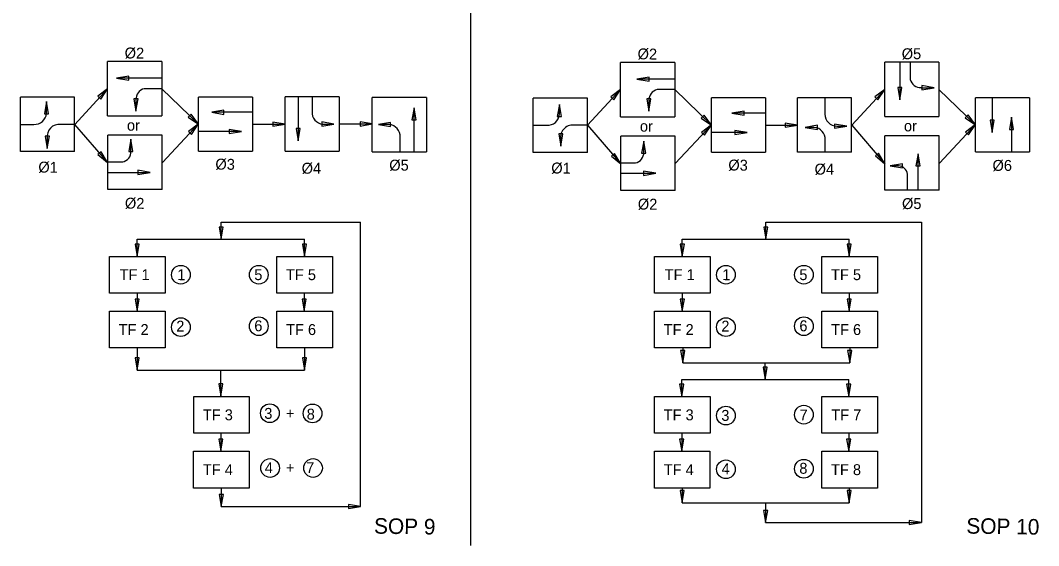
# Model space of a CAD drawing. Extents: x 10027 to 10796, y 10033 to 10528.
# Drawn here: x 10043.8 to 10370.4, y 10033.4 to 10201.8 of the extents above; entities that cross this region are included whole.
import ezdxf

# ---------------------------------------------------------------- set-up
doc = ezdxf.new("R2010")
doc.units = 0
for name, color, linetype in [('AdhocPoint_dp', 7, 'Continuous'), ('Default', 7, 'Continuous'), ('Dimension', 7, 'Continuous'), ('DSIndex', 7, 'Continuous'), ('PlotBorder_dp', 7, 'Continuous')]:
    doc.layers.add(name, color=color, linetype=linetype)

msp = doc.modelspace()

# ---------------------------------------------------------------- linework, layer by layer
at = {"layer": 'AdhocPoint_dp'}
msp.add_line((10188.25, 10033.43), (10188.25, 10528.43), dxfattribs=at)
at = {"layer": 'Default'}
for p, q in [((10071.81, 10171.23), (10071.81, 10188.62)), ((10089.2, 10188.62), (10071.81, 10188.62)), ((10089.2, 10188.62), (10089.2, 10171.23)), ((10236.32, 10170.93), (10236.32, 10188.33)), ((10253.71, 10188.33), (10236.32, 10188.33)), ((10253.71, 10188.33), (10253.71, 10170.93)), ((10321.01, 10171.01), (10321.01, 10188.4)), ((10338.41, 10188.4), (10321.01, 10188.4)), ((10325.85, 10188.4), (10325.85, 10176.39)), ((10329.22, 10188.4), (10329.22, 10182.92)), ((10338.41, 10188.4), (10338.41, 10171.01)), ((10089.21, 10183.29), (10074.69, 10183.29)), ((10253.72, 10183), (10241.53, 10183)), ((10061.27, 10168.48), (10071.81, 10179.92)), ((10089.21, 10179.92), (10083.54, 10179.92)), ((10089.21, 10179.92), (10100.91, 10168.55)), ((10225.72, 10168.19), (10236.32, 10179.69)), ((10253.72, 10179.63), (10248.05, 10179.63)), ((10253.72, 10179.63), (10265.42, 10168.26)), ((10310.44, 10168.23), (10321.01, 10179.71)), ((10338.41, 10179.71), (10350.11, 10168.33)), ((10061.21, 10177.18), (10043.81, 10177.18)), ((10043.81, 10159.78), (10043.81, 10177.18)), ((10061.21, 10159.78), (10061.21, 10177.18)), ((10080.88, 10176.37), (10080.88, 10172.72)), ((10100.91, 10159.85), (10100.91, 10177.25)), ((10118.3, 10177.25), (10100.91, 10177.25)), ((10118.3, 10177.25), (10118.3, 10159.85)), ((10128.71, 10159.91), (10128.71, 10177.3)), ((10146.1, 10177.3), (10128.71, 10177.3)), ((10132.91, 10177.3), (10132.91, 10163.2)), ((10137.36, 10177.3), (10137.36, 10172.6)), ((10146.1, 10177.3), (10146.1, 10159.91)), ((10156.66, 10159.7), (10156.66, 10177.1)), ((10174.06, 10177.1), (10156.66, 10177.1)), ((10174.06, 10177.1), (10174.06, 10159.7)), ((10225.72, 10176.88), (10208.33, 10176.88)), ((10208.33, 10159.49), (10208.33, 10176.88)), ((10225.72, 10159.49), (10225.72, 10176.88)), ((10265.42, 10159.56), (10265.42, 10176.96)), ((10282.81, 10176.96), (10265.42, 10176.96)), ((10282.81, 10176.96), (10282.81, 10159.56)), ((10310.41, 10176.96), (10293.02, 10176.96)), ((10293.02, 10159.56), (10293.02, 10176.96)), ((10301.82, 10176.96), (10301.82, 10171.74)), ((10310.41, 10159.56), (10310.41, 10176.96)), ((10350.11, 10159.64), (10350.11, 10177.03)), ((10367.51, 10177.03), (10350.11, 10177.03)), ((10355.51, 10177.03), (10355.51, 10165.9)), ((10367.51, 10177.03), (10367.51, 10159.64)), ((10052.17, 10171.99), (10052.17, 10175.79)), ((10170.07, 10159.7), (10170.07, 10173.8)), ((10071.81, 10171.23), (10089.2, 10171.23)), ((10118.3, 10172.36), (10105.18, 10172.36)), ((10216.68, 10171.7), (10216.68, 10172.12)), ((10236.32, 10170.93), (10253.71, 10170.93)), ((10282.81, 10172.07), (10272.02, 10172.07)), ((10321.01, 10171.01), (10338.41, 10171.01)), ((10361.67, 10170.77), (10361.67, 10159.64)), ((10043.81, 10168.48), (10048.16, 10168.48)), ((10061.21, 10168.48), (10056.7, 10168.48)), ((10061.21, 10168.48), (10071.74, 10156.28)), ((10089.36, 10156.28), (10100.85, 10168.55)), ((10118.3, 10168.55), (10128.71, 10168.55)), ((10140.87, 10168.58), (10142.01, 10168.58)), ((10142.01, 10168.58), (10144.37, 10168.58)), ((10146.1, 10168.61), (10156.66, 10168.61)), ((10160.98, 10168.42), (10158.62, 10168.42)), ((10162.12, 10168.42), (10160.98, 10168.42)), ((10208.33, 10168.19), (10212.67, 10168.19)), ((10225.72, 10168.19), (10221.79, 10168.19)), ((10225.72, 10168.19), (10236.4, 10155.81)), ((10253.87, 10155.98), (10265.42, 10168.32)), ((10282.81, 10168.26), (10293.02, 10168.26)), ((10310.44, 10168.23), (10321.1, 10155.88)), ((10338.56, 10156.06), (10350.11, 10168.4)), ((10052.45, 10164.03), (10052.45, 10160.76)), ((10089.29, 10164.97), (10071.89, 10164.97)), ((10071.89, 10147.58), (10071.89, 10164.97)), ((10079.22, 10160.02), (10079.22, 10163.73)), ((10089.29, 10147.58), (10089.29, 10164.97)), ((10114.71, 10166.19), (10101.12, 10166.19)), ((10165.63, 10159.7), (10165.63, 10164.41)), ((10253.8, 10164.68), (10236.4, 10164.68)), ((10236.4, 10147.29), (10236.4, 10164.68)), ((10243.73, 10159.57), (10243.73, 10163.12)), ((10253.8, 10147.29), (10253.8, 10164.68)), ((10276.89, 10165.9), (10265.42, 10165.9)), ((10301.91, 10159.56), (10301.91, 10163.52)), ((10338.49, 10164.76), (10321.1, 10164.76)), ((10321.1, 10147.36), (10321.1, 10164.76)), ((10338.49, 10147.36), (10338.49, 10164.76)), ((10061.21, 10159.78), (10043.81, 10159.78)), ((10100.91, 10159.85), (10118.3, 10159.85)), ((10128.71, 10159.91), (10146.1, 10159.91)), ((10156.66, 10159.7), (10174.06, 10159.7)), ((10071.89, 10156.46), (10076.67, 10156.46)), ((10225.72, 10159.49), (10208.33, 10159.49)), ((10265.42, 10159.56), (10282.81, 10159.56)), ((10310.41, 10159.56), (10293.02, 10159.56)), ((10331.7, 10147.36), (10331.7, 10159.06)), ((10350.11, 10159.64), (10367.51, 10159.64)), ((10236.4, 10156.16), (10241.05, 10156.16)), ((10071.89, 10153.09), (10085.41, 10153.09)), ((10236.4, 10152.8), (10247.59, 10152.8)), ((10328.34, 10147.36), (10328.34, 10152.52)), ((10089.29, 10147.58), (10071.89, 10147.58)), ((10253.8, 10147.29), (10236.4, 10147.29)), ((10338.49, 10147.36), (10321.1, 10147.36)), ((10108.19, 10131.66), (10108.19, 10137.16)), ((10108.19, 10137.16), (10152.95, 10137.16)), ((10282.88, 10131.66), (10282.88, 10137.16)), ((10282.88, 10137.16), (10332.81, 10137.16)), ((10332.81, 10137.16), (10332.81, 10040.82)), ((10081.3, 10126.17), (10081.3, 10131.66)), ((10081.3, 10131.66), (10134.96, 10131.66)), ((10134.96, 10126.17), (10134.96, 10131.66)), ((10256.11, 10126.17), (10256.11, 10131.66)), ((10256.11, 10131.66), (10309.65, 10131.66)), ((10309.65, 10126.17), (10309.65, 10131.66)), ((10081.3, 10114.41), (10081.3, 10108.58)), ((10134.84, 10114.41), (10134.84, 10108.58)), ((10256.11, 10114.41), (10256.11, 10108.58)), ((10309.65, 10114.41), (10309.65, 10108.58)), ((10081.3, 10096.82), (10081.3, 10089.73)), ((10134.96, 10096.82), (10134.96, 10089.73)), ((10256.24, 10096.82), (10256.24, 10092.07)), ((10309.79, 10096.82), (10309.79, 10092.07)), ((10256.24, 10092.07), (10309.79, 10092.07)), ((10282.69, 10086.74), (10282.69, 10092.07)), ((10081.3, 10089.73), (10134.96, 10089.73)), ((10108.13, 10081.24), (10108.13, 10089.73)), ((10255.92, 10081.24), (10255.92, 10086.74)), ((10255.92, 10086.74), (10309.47, 10086.74)), ((10309.47, 10081.24), (10309.47, 10086.74)), ((10108.13, 10069.49), (10108.13, 10063.66)), ((10255.92, 10069.49), (10255.92, 10063.66)), ((10309.47, 10069.49), (10309.47, 10063.66)), ((10108.26, 10051.9), (10108.26, 10045.94)), ((10256.06, 10051.9), (10256.06, 10047.15)), ((10309.6, 10051.9), (10309.6, 10047.15)), ((10108.26, 10045.94), (10152.95, 10045.94)), ((10256.06, 10047.15), (10309.6, 10047.15)), ((10282.83, 10047.15), (10282.83, 10040.82)), ((10282.83, 10040.82), (10332.81, 10040.82))]:
    msp.add_line(p, q, dxfattribs=at)
for centre, radius, start, end in [((10332.57, 10183.69), 3.44, 192.998, 272.3331), ((10084.32, 10176.57), 3.44, 102.998, 183.455), ((10248.83, 10176.28), 3.44, 102.998, 182.423), ((10048.4, 10172.25), 3.78, 266.3242, 356.0955), ((10141.13, 10172.35), 3.78, 176.3242, 266.0955), ((10212.91, 10171.96), 3.78, 266.3242, 356.0955), ((10305.7, 10171.8), 3.88, 180.9326, 269.1625), ((10056.29, 10164.62), 3.88, 83.8256, 188.6991), ((10161.86, 10164.65), 3.78, 356.3242, 86.0955), ((10220.95, 10164.39), 3.88, 77.6405, 189.221), ((10298.14, 10163.76), 3.78, 356.3242, 86.0955), ((10076.07, 10159.59), 3.16, 278.4278, 5.0512), ((10240.58, 10159.29), 3.16, 278.4278, 5.0512), ((10325.21, 10152.06), 3.16, 8.4277, 86.4044)]:
    msp.add_arc(centre, radius, start, end, dxfattribs=at)
at = {"layer": 'Dimension'}
for p, q in [((10332.71, 10180.25), (10336.85, 10180.25)), ((10245.39, 10176.14), (10245.39, 10172.77)), ((10216.68, 10172.12), (10216.68, 10174.9)), ((10298.39, 10167.53), (10295.52, 10167.53)), ((10305.64, 10167.92), (10308.83, 10167.92)), ((10217.12, 10163.77), (10217.12, 10161.49)), ((10325.41, 10155.22), (10322.78, 10155.22)), ((10152.95, 10045.94), (10152.95, 10137.16))]:
    msp.add_line(p, q, dxfattribs=at)
for centre in [(10095.28, 10120.29), (10120.28, 10120.29), (10270.09, 10120.29), (10295.09, 10120.29), (10095.28, 10103.48), (10120.28, 10103.77), (10270.09, 10103.48), (10295.09, 10103.77), (10123.83, 10075.89), (10137.51, 10075.82), (10270.09, 10075.12), (10295.09, 10075.41), (10123.9, 10058.31), (10137.68, 10058.31), (10270.09, 10057.9), (10295.09, 10058.08)]:
    msp.add_circle(centre, 3, dxfattribs=at)
at = {"layer": 'DSIndex'}
for points in [[(10072.39, 10126.17), (10090.21, 10126.17), (10090.21, 10114.41), (10072.39, 10114.41)], [(10126.04, 10126.17), (10143.87, 10126.17), (10143.87, 10114.41), (10126.04, 10114.41)], [(10247.2, 10126.17), (10265.02, 10126.17), (10265.02, 10114.41), (10247.2, 10114.41)], [(10300.85, 10126.17), (10318.68, 10126.17), (10318.68, 10114.41), (10300.85, 10114.41)], [(10072.39, 10108.58), (10090.21, 10108.58), (10090.21, 10096.82), (10072.39, 10096.82)], [(10126.04, 10108.58), (10143.87, 10108.58), (10143.87, 10096.82), (10126.04, 10096.82)], [(10247.2, 10108.58), (10265.02, 10108.58), (10265.02, 10096.82), (10247.2, 10096.82)], [(10300.85, 10108.58), (10318.68, 10108.58), (10318.68, 10096.82), (10300.85, 10096.82)], [(10099.4, 10081.24), (10117.22, 10081.24), (10117.22, 10069.49), (10099.4, 10069.49)], [(10247.2, 10081.24), (10265.02, 10081.24), (10265.02, 10069.49), (10247.2, 10069.49)], [(10300.85, 10081.24), (10318.68, 10081.24), (10318.68, 10069.49), (10300.85, 10069.49)], [(10099.35, 10063.66), (10117.17, 10063.66), (10117.17, 10051.9), (10099.35, 10051.9)], [(10247.14, 10063.66), (10264.97, 10063.66), (10264.97, 10051.9), (10247.14, 10051.9)], [(10300.85, 10063.66), (10318.68, 10063.66), (10318.68, 10051.9), (10300.85, 10051.9)]]:
    msp.add_lwpolyline(points, close=True, dxfattribs=at)
at = {"layer": 'PlotBorder_dp'}
for points in [[(10074.69, 10183.29), (10078.6, 10182.63), (10078.6, 10183.95)], [(10241.53, 10183), (10245.44, 10182.33), (10245.44, 10183.66)], [(10071.81, 10179.92), (10068.68, 10177.5), (10069.65, 10176.6)], [(10236.32, 10179.69), (10233.19, 10177.27), (10234.16, 10176.37)], [(10321.01, 10179.71), (10317.88, 10177.28), (10318.85, 10176.39)], [(10325.85, 10176.39), (10326.51, 10180.3), (10325.19, 10180.3)], [(10336.85, 10180.25), (10332.95, 10180.92), (10332.95, 10179.59)], [(10080.88, 10172.72), (10081.55, 10176.63), (10080.22, 10176.63)], [(10245.39, 10172.77), (10246.05, 10176.68), (10244.73, 10176.68)], [(10052.17, 10175.79), (10051.51, 10171.88), (10052.83, 10171.88)], [(10105.18, 10172.36), (10109.09, 10171.7), (10109.09, 10173.02)], [(10170.07, 10173.8), (10169.41, 10169.9), (10170.74, 10169.9)], [(10216.68, 10174.9), (10216.02, 10171), (10217.34, 10171)], [(10100.91, 10168.55), (10098.57, 10171.75), (10097.65, 10170.8)], [(10265.42, 10168.26), (10263.08, 10171.46), (10262.16, 10170.51)], [(10272.02, 10172.07), (10275.93, 10171.41), (10275.93, 10172.73)], [(10350.11, 10168.33), (10347.77, 10171.53), (10346.85, 10170.58)], [(10355.51, 10165.9), (10356.17, 10169.8), (10354.84, 10169.8)], [(10361.67, 10170.77), (10361.01, 10166.86), (10362.33, 10166.86)], [(10100.85, 10168.55), (10097.7, 10166.15), (10098.66, 10165.25)], [(10114.71, 10166.19), (10110.8, 10166.86), (10110.8, 10165.53)], [(10128.71, 10168.55), (10124.8, 10169.21), (10124.8, 10167.89)], [(10132.91, 10163.2), (10133.58, 10167.11), (10132.25, 10167.11)], [(10144.37, 10168.58), (10140.46, 10169.25), (10140.46, 10167.92)], [(10156.66, 10168.61), (10152.76, 10169.27), (10152.76, 10167.94)], [(10158.62, 10168.42), (10162.52, 10167.76), (10162.52, 10169.08)], [(10265.42, 10168.32), (10262.27, 10165.92), (10263.23, 10165.02)], [(10276.89, 10165.9), (10272.99, 10166.56), (10272.99, 10165.24)], [(10293.02, 10168.26), (10289.11, 10168.92), (10289.11, 10167.6)], [(10295.52, 10167.53), (10299.43, 10166.87), (10299.43, 10168.19)], [(10308.83, 10167.92), (10304.92, 10168.58), (10304.92, 10167.26)], [(10350.11, 10168.4), (10346.96, 10166), (10347.92, 10165.09)], [(10350.11, 10168.4), (10346.96, 10166), (10347.92, 10165.09)], [(10052.45, 10160.76), (10053.11, 10164.66), (10051.79, 10164.66)], [(10079.22, 10163.73), (10078.56, 10159.83), (10079.88, 10159.83)], [(10217.12, 10161.49), (10217.78, 10165.4), (10216.46, 10165.4)], [(10243.73, 10163.12), (10243.07, 10159.22), (10244.39, 10159.22)], [(10071.74, 10156.28), (10069.69, 10159.67), (10068.69, 10158.8)], [(10236.4, 10155.81), (10234.35, 10159.19), (10233.35, 10158.33)], [(10321.1, 10155.88), (10319.05, 10159.27), (10318.04, 10158.4)], [(10331.7, 10159.06), (10331.04, 10155.16), (10332.37, 10155.16)], [(10085.41, 10153.09), (10081.51, 10153.76), (10081.51, 10152.43)], [(10247.59, 10152.8), (10243.69, 10153.46), (10243.69, 10152.14)], [(10322.78, 10155.22), (10326.68, 10154.55), (10326.68, 10155.88)], [(10108.19, 10131.66), (10108.85, 10135.57), (10107.52, 10135.57)], [(10282.88, 10131.66), (10283.54, 10135.57), (10282.22, 10135.57)], [(10081.3, 10126.17), (10081.96, 10130.07), (10080.64, 10130.07)], [(10134.96, 10126.17), (10135.62, 10130.07), (10134.29, 10130.07)], [(10256.11, 10126.17), (10256.77, 10130.07), (10255.45, 10130.07)], [(10309.65, 10126.17), (10310.31, 10130.07), (10308.99, 10130.07)], [(10081.3, 10108.58), (10081.96, 10112.49), (10080.64, 10112.49)], [(10134.84, 10108.58), (10135.5, 10112.49), (10134.18, 10112.49)], [(10256.11, 10108.58), (10256.77, 10112.49), (10255.45, 10112.49)], [(10309.65, 10108.58), (10310.31, 10112.49), (10308.99, 10112.49)], [(10256.24, 10092.07), (10256.9, 10095.98), (10255.58, 10095.98)], [(10309.79, 10092.07), (10310.45, 10095.98), (10309.12, 10095.98)], [(10081.3, 10089.73), (10081.96, 10093.63), (10080.64, 10093.63)], [(10134.96, 10089.73), (10135.62, 10093.63), (10134.29, 10093.63)], [(10282.69, 10086.74), (10283.36, 10090.64), (10282.03, 10090.64)], [(10108.13, 10081.38), (10108.79, 10085.28), (10107.46, 10085.28)], [(10255.92, 10081.24), (10256.58, 10085.15), (10255.26, 10085.15)], [(10309.47, 10081.24), (10310.13, 10085.15), (10308.8, 10085.15)], [(10108.13, 10063.66), (10108.79, 10067.56), (10107.46, 10067.56)], [(10255.92, 10063.66), (10256.58, 10067.56), (10255.26, 10067.56)], [(10309.47, 10063.66), (10310.13, 10067.56), (10308.8, 10067.56)], [(10108.26, 10045.94), (10108.92, 10049.85), (10107.6, 10049.85)], [(10256.06, 10047.15), (10256.72, 10051.05), (10255.4, 10051.05)], [(10309.6, 10047.15), (10310.26, 10051.05), (10308.94, 10051.05)], [(10152.95, 10045.94), (10149.05, 10046.6), (10149.05, 10045.28)], [(10282.83, 10040.82), (10283.49, 10044.73), (10282.17, 10044.73)], [(10332.81, 10040.82), (10328.9, 10041.49), (10328.9, 10040.16)]]:
    msp.add_lwpolyline(points, close=True, dxfattribs=at)

# ---------------------------------------------------------------- texts
at = {"layer": 'Default'}
for s, p in [('SOP 9', (10157.22, 10037.27)), ('SOP 10', (10347.18, 10037.29))]:
    msp.add_text(s, height=5, rotation=359.1183, dxfattribs=at).set_placement(p)
at = {"layer": 'Dimension'}
for s, rotation, p in [('Ø2', 359.1183, (10077.24, 10189.64)), ('Ø2', 359.1183, (10241.75, 10189.35)), ('or', 359.1183, (10077.97, 10166.47)), ('or', 359.1183, (10242.48, 10166.18)), ('or', 359.1183, (10327.18, 10166.25)), ('Ø1', 359.1183, (10049.56, 10153.05)), ('Ø3', 359.1183, (10106.34, 10154)), ('Ø3', 359.1183, (10270.85, 10153.71)), ('Ø1', 359.1183, (10214.07, 10152.76)), ('Ø2', 359.1183, (10077.32, 10141.49)), ('Ø2', 359.1183, (10241.83, 10141.2)), ('1', 359.6943, (10094.12, 10118.54)), ('5', 359.6943, (10118.82, 10118.55)), ('1', 359.6943, (10268.93, 10118.54)), ('5', 359.6943, (10293.63, 10118.55)), ('2', 359.6943, (10093.8, 10102.04)), ('6', 359.6943, (10118.84, 10102.17)), ('2', 359.6943, (10268.61, 10102.04)), ('6', 359.6943, (10293.65, 10102.17)), ('3', 359.6943, (10122.03, 10074.08)), ('8', 359.6943, (10135.64, 10073.84)), ('3', 359.6943, (10268.61, 10073.43)), ('7', 359.6943, (10293.7, 10073.56)), ('4', 359.6943, (10122.2, 10056.67)), ('7', 359.6943, (10135.45, 10056.67)), ('4', 359.6943, (10268.68, 10056.3)), ('8', 359.6943, (10293.63, 10056.47))]:
    msp.add_text(s, height=3.5, rotation=rotation, dxfattribs=at).set_placement(p)
for s, p in [('Ø5', (10326.48, 10189.37)), ('Ø5', (10162.13, 10153.66)), ('Ø6', (10355.6, 10153.57)), ('Ø4', (10134.03, 10152.67)), ('Ø4', (10298.54, 10152.38)), ('Ø5', (10326.57, 10141.33)), ('TF 1', (10075.65, 10118.54)), ('TF 5', (10129, 10118.54)), ('TF 1', (10250.46, 10118.54)), ('TF 5', (10303.81, 10118.54)), ('TF 2', (10075.33, 10100.95)), ('TF 6', (10129.03, 10100.95)), ('TF 2', (10250.14, 10100.95)), ('TF 6', (10303.83, 10100.95)), ('TF 3', (10102.34, 10073.61)), ('+', (10128.97, 10074.07)), ('TF 3', (10250.14, 10073.61)), ('TF 7', (10303.88, 10073.61)), ('TF 4', (10102.36, 10056.03)), ('+', (10128.97, 10056.67)), ('TF 4', (10250.16, 10056.03)), ('TF 8', (10303.81, 10056.03))]:
    msp.add_text(s, height=3.5, dxfattribs=at).set_placement(p)

doc.saveas('drawing.dxf')
